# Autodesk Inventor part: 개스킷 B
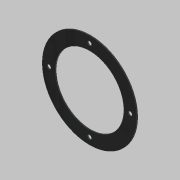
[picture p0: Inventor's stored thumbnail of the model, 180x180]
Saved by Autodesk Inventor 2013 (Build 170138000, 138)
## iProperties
Created: 2019-02
Part Number: 개스킷 B
Material: 고무
Document SubType Name: Modeling
Designer: mduedu
Density: 1 g/cm^3
Author: mduedu
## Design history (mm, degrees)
sketch "스케치1"
  geometry: C1 r 52.5 at (0, 0); C2 r 38 at (0, 0); 1 further point
  constraints: 2 centre point, 2 coincident
  dimensions: "d0" = 105 diameter of C1; "d1" = 76 diameter of C2
extrude "돌출1" new body sketch "스케치1" distance "d2" = 1; taper "d3" = 0 deg
sketch "스케치2" dims "d4" = 90
  geometry: 3 further points
  constraints: 2 vertical alignment, 1 coincident, 2 other
hole "구멍1" sketch "스케치2" at (0, 45) diameter "d5" = 4.5; stored, may be unused: countersink angle "d9" = 90 deg, drill point angle "d11" = 118 deg; dims "d6" = 6, "d7" = 4, "d8" = 2, "d10" = 8
node "솔리드1"
pattern_circular "원형 패턴1" dims angle "d13" = 360 deg
